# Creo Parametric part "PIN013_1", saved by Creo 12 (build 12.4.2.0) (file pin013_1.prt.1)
Units: Custom; MM, KILOGRAM, SECS

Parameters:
  PTC_WM_ITERATION = "0"
  PTC_WM_VERSION = "-.0"
  PTC_WM_LIFECYCLE_STATE = "In Work"
  PTC_WM_LIFECYCLE = "MO_CADDocument"
  PTC_WM_CREATED_BY = "Maximilian Roepper (Z0017RMS: MO)"
  PTC_WM_CREATED_ON = "18-Sep-26 11:36:42 AM"
  PTC_WM_MODIFIED_BY = "Maximilian Roepper (Z0017RMS: MO)"
  PTC_WM_MODIFIED_ON = "18-Sep-26 11:36:46 AM"
  PDMLINKNUMBER = "PDM000071455213"
  PTC_WM_NAME = "pin013_1.prt"
  PTC_WM_NUMBER = "PDM000071455213"

Other parameters: WEIGHT, WEIGHT_FACTOR, WEIGHT_ADD, _MASS_TEMP, _DIFF_TEMP, MC_ERRORS, SUPPLIER

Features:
  1. coordinate system
  2. datum plane "PRT_YZ"
  3. datum plane "PRT_XY"
  4. datum plane "PRT_XZ"
  5. coordinate system
  6. datum axis
  7. datum axis
  8. datum axis
  9. coordinate system
  10. imported feature

Other named items: PRT, SIEMENS_MO, DRW_VIEW_ORG, PRT_X, PRT_Y, PRT_Z, CS0, ROUGH_GROB

Layers: 00_STD_CSYS-KSYS, 01_STD_PLANES-EBENEN, 02_STD_AXES-ACHSEN, 03_STD_CSYS-KSYS, 24_IMPORT_FEAT-IMPORT_KE

Surfaces: 14 plane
